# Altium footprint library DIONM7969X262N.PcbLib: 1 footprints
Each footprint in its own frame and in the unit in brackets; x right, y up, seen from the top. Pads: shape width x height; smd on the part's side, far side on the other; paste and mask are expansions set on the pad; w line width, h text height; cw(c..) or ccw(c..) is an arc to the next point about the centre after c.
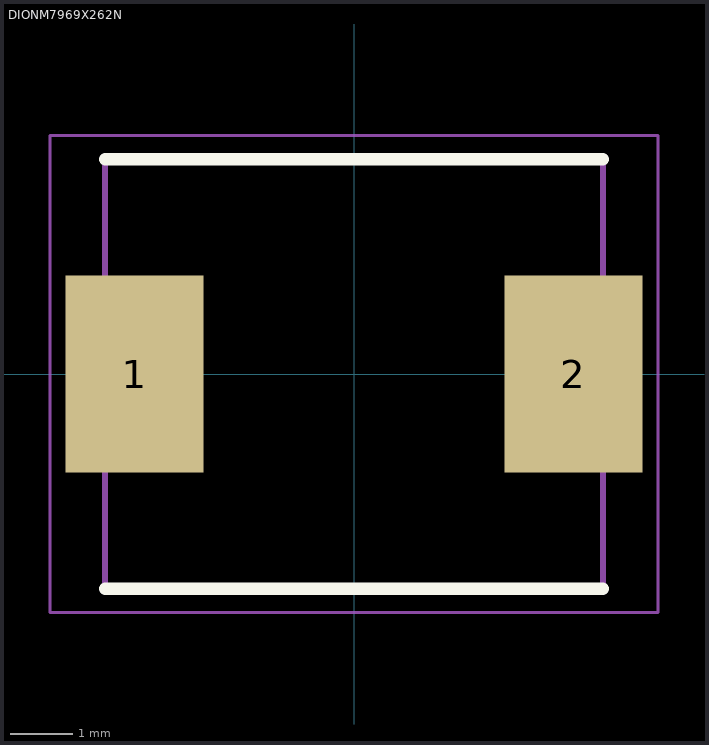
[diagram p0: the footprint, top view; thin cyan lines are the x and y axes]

## DIONM7969X262N [mm]
pads (2):
  rect 2.2x3.15 smd: 1(-3.5,0) 2(3.5,0)
Top Overlay:
  lines w0.2: -3.97,-3.428 3.97,-3.428 ; -3.97,3.428 3.97,3.428
Mechanical 15:
  lines w0.1: -3.97,-3.428 3.97,-3.428 3.97,3.428 -3.97,3.428 -3.97,-3.428
Mechanical 20:
  lines w0.05: -4.85,-3.805 4.85,-3.805 4.85,3.805 -4.85,3.805 -4.85,-3.805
